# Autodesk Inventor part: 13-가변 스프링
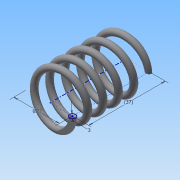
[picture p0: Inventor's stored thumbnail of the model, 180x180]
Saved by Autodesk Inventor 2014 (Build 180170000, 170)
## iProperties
Created: 2015-09
Part Number: 13-가변 스프링
Material: 강철, 탄소
Document SubType Name: Modeling
Designer: study
Density: 7.87 g/cm^3
Appearance: 반연마
Mass: 18.7944 g
Surface Area: 32.46 cm^2
Volume: 2.38811 cm^3
Author: study
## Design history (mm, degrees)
sketch "스케치1"
  geometry: L1 (0, 0)-(11, 0); L2 (11, 0)-(11, 28.411); L3 (11, 28.411)-(0, 28.411); L4 (0, 28.411)-(0, 0); C1 r 1.5 at (11, 0)
  constraints: 8 end point, 2 parallel, 1 centre point, 1 coincident, 1 horizontal, 1 perpendicular
  dimensions: "d0" = 28.4112 distance of L1.end L2.end (derived); "d1" = 22 diameter of L2 L4; "d2" = 3 diameter of C1
feature "코일1" sketch "스케치1" pitch "d3" = 10; turns "d5" = 5; dims "d4" = 28.4112 (= d0), "d6" = 0, angle "d7" = 90 deg, angle "d8" = 90 deg, "d9" = 0, "d10" = 0
node "작업 평면1"
sketch "스케치2"
  geometry: L1 (-12.5, 0)-(-9.5, 0) reference; 1 further point
  constraints: 1 horizontal alignment
extrude "돌출1" cut sketch "스케치2" stored distance "d12" = 10; taper "d13" = 0 deg
node "작업 평면2"
sketch "스케치3"
  geometry: L1 (-9.5, 0)-(-12.5, 0) reference; 1 further point
  constraints: 1 horizontal alignment
extrude "돌출2" cut sketch "스케치3" stored distance "d15" = 10; taper "d16" = 0 deg
node "솔리드1"
node "절단 모서리 투영1"
node "절단 모서리 투영2"
other parameters: "d11" = 0, "d14" = 28.4112 (= d0)
